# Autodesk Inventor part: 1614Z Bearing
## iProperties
Created: 2009-03
Part Number: 1614Z Bearing
Document SubType Name: Modeling
Designer: Pat
Density: 1 g/cm^3
Author: Pat
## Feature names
1. Base1
